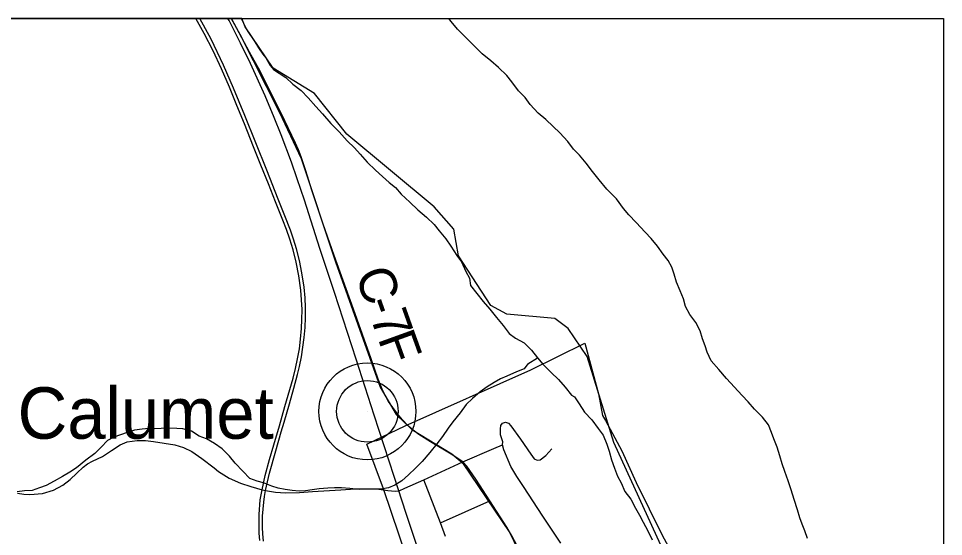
# Model space of a CAD drawing. Extents: x 2.1 to 8.9, y 14.1 to 20.9.
# Drawn here: x 7.48 to 8.9, y 20.105 to 20.9 of the extents above; entities that cross this region are included whole.
import ezdxf

# ---------------------------------------------------------------- set-up
doc = ezdxf.new("R2010")
doc.units = 0
for name, color, linetype in [('Default', 7, 'Continuous'), ('GM_X_Major_River', 7, 'Continuous'), ('GM_X_Minor_River', 7, 'Continuous'), ('GM_X_Rail_Line_Text', 7, 'Continuous'), ('GM_X_State_Location', 7, 'Continuous'), ('GM_X_State_Route', 7, 'Continuous'), ('GM_X_State_Shield', 7, 'Continuous'), ('GM_X_Township_Road', 7, 'Continuous'), ('GM_X_Township_Text', 7, 'Continuous'), ('GM_X_Unincorporated_Text', 7, 'Continuous'), ('SC_Shading1', 7, 'Continuous'), ('SH_Cut_Line', 7, 'Continuous'), ('SH_Data', 7, 'Continuous'), ('TX_P_Misc', 7, 'Continuous')]:
    doc.layers.add(name, color=color, linetype=linetype)

msp = doc.modelspace()

# ---------------------------------------------------------------- linework, layer by layer
at = {"layer": 'Default'}
for p, q in [((7.8225, 20.9), (2.1, 20.9)), ((7.8279, 20.8874), (7.8225, 20.9)), ((7.8709, 20.824), (7.8279, 20.8874)), ((7.9341, 20.7849), (7.8709, 20.824)), ((7.984, 20.7223), (7.9341, 20.7849)), ((8.1182, 20.6111), (7.984, 20.7223)), ((8.1484, 20.5766), (8.1182, 20.6111)), ((8.1552, 20.5359), (8.1484, 20.5766)), ((8.205, 20.4597), (8.1552, 20.5359)), ((8.2298, 20.4464), (8.205, 20.4597)), ((8.3034, 20.4395), (8.2298, 20.4464)), ((8.3237, 20.4245), (8.3034, 20.4395)), ((8.3529, 20.3814), (8.3237, 20.4245)), ((8.3941, 20.2491), (8.3529, 20.3814)), ((8.4717, 20.0797), (8.3941, 20.2491))]:
    msp.add_line(p, q, dxfattribs=at)
at = {"layer": 'GM_X_Rail_Line_Text'}
for p, q in [((7.7649, 20.877), (7.7523, 20.9)), ((7.7754, 20.8683), (7.7584, 20.9)), ((7.7785, 20.8502), (7.7649, 20.877)), ((7.7948, 20.8282), (7.7754, 20.8683)), ((7.7915, 20.8227), (7.7785, 20.8502)), ((7.8037, 20.7945), (7.7915, 20.8227)), ((7.81, 20.7933), (7.7948, 20.8282)), ((7.8152, 20.7667), (7.8037, 20.7945)), ((7.8272, 20.751), (7.81, 20.7933)), ((7.8266, 20.7383), (7.8152, 20.7667)), ((7.844, 20.7094), (7.8272, 20.751)), ((7.8406, 20.7032), (7.8266, 20.7383)), ((7.8609, 20.6671), (7.844, 20.7094)), ((7.8519, 20.6748), (7.8406, 20.7032)), ((7.8634, 20.6465), (7.8519, 20.6748)), ((7.8785, 20.6229), (7.8609, 20.6671)), ((7.8745, 20.6187), (7.8634, 20.6465)), ((7.8889, 20.5972), (7.8785, 20.6229)), ((7.8856, 20.5906), (7.8745, 20.6187)), ((7.8972, 20.5753), (7.8889, 20.5972)), ((7.8911, 20.5764), (7.8856, 20.5906)), ((7.8962, 20.5616), (7.8911, 20.5764)), ((7.902, 20.5613), (7.8972, 20.5753)), ((7.9014, 20.5452), (7.8962, 20.5616)), ((7.9064, 20.5466), (7.902, 20.5613)), ((7.9061, 20.5263), (7.9014, 20.5452)), ((7.9112, 20.5284), (7.9064, 20.5466)), ((7.9101, 20.5052), (7.9061, 20.5263)), ((7.915, 20.5095), (7.9112, 20.5284)), ((7.9184, 20.4879), (7.915, 20.5095)), ((7.9133, 20.4829), (7.9101, 20.5052)), ((7.9145, 20.4682), (7.9133, 20.4829)), ((7.9198, 20.4715), (7.9184, 20.4879)), ((7.9151, 20.4534), (7.9145, 20.4682)), ((7.9204, 20.4565), (7.9198, 20.4715)), ((7.9149, 20.4383), (7.9151, 20.4534)), ((7.9204, 20.441), (7.9204, 20.4565)), ((7.9143, 20.4242), (7.9149, 20.4383)), ((7.9197, 20.4258), (7.9204, 20.441)), ((7.9129, 20.4077), (7.9143, 20.4242)), ((7.9185, 20.4107), (7.9197, 20.4258)), ((7.9166, 20.3955), (7.9185, 20.4107)), ((7.911, 20.393), (7.9129, 20.4077)), ((7.9143, 20.381), (7.9166, 20.3955)), ((7.9082, 20.3779), (7.911, 20.393)), ((7.9113, 20.3659), (7.9143, 20.381)), ((7.905, 20.3629), (7.9082, 20.3779)), ((7.9083, 20.3538), (7.9113, 20.3659)), ((7.9013, 20.3482), (7.905, 20.3629)), ((7.9028, 20.3325), (7.9083, 20.3538)), ((7.8966, 20.3308), (7.9013, 20.3482)), ((7.8889, 20.3045), (7.8966, 20.3308)), ((7.896, 20.3088), (7.9028, 20.3325)), ((7.8875, 20.2805), (7.896, 20.3088)), ((7.8803, 20.2751), (7.8889, 20.3045)), ((7.8831, 20.2656), (7.8875, 20.2805)), ((7.8718, 20.246), (7.8803, 20.2751)), ((7.8748, 20.2367), (7.8831, 20.2656)), ((7.8653, 20.2231), (7.8718, 20.246)), ((7.8651, 20.2024), (7.8748, 20.2367)), ((7.8584, 20.1986), (7.8653, 20.2231)), ((7.8537, 20.1766), (7.8584, 20.1986)), ((7.8591, 20.1756), (7.8651, 20.2024)), ((7.8511, 20.1613), (7.8537, 20.1766)), ((7.8563, 20.1577), (7.8577, 20.1667)), ((7.8577, 20.1667), (7.8591, 20.1756)), ((7.8495, 20.1387), (7.8511, 20.1613)), ((7.8546, 20.1364), (7.8563, 20.1577)), ((7.8492, 20.1199), (7.8495, 20.1387)), ((7.8546, 20.1189), (7.8546, 20.1364)), ((7.8494, 20.1101), (7.8492, 20.1199)), ((7.8505, 20.0989), (7.8494, 20.1101)), ((7.8548, 20.1091), (7.8546, 20.1189)), ((7.8559, 20.0979), (7.8548, 20.1091))]:
    msp.add_line(p, q, dxfattribs=at)
at = {"layer": 'GM_X_State_Location'}
for p, q in [((7.8215, 20.9), (7.8307, 20.8817)), ((8.1442, 20.8953), (8.1404, 20.9)), ((8.1539, 20.8834), (8.1442, 20.8953)), ((7.8307, 20.8817), (7.8425, 20.8642)), ((8.1666, 20.8711), (8.1539, 20.8834)), ((7.8425, 20.8642), (7.8481, 20.8551)), ((8.1798, 20.8577), (8.1666, 20.8711)), ((7.8481, 20.8551), (7.8551, 20.8451)), ((8.1918, 20.8458), (8.1798, 20.8577)), ((7.8551, 20.8451), (7.8594, 20.8394)), ((7.8594, 20.8394), (7.8664, 20.8281)), ((8.2052, 20.835), (8.1918, 20.8458)), ((8.2168, 20.825), (8.2052, 20.835)), ((7.8664, 20.8281), (7.8712, 20.822)), ((7.8712, 20.822), (7.8904, 20.8097)), ((8.2295, 20.8124), (8.2168, 20.825)), ((7.8904, 20.8097), (7.9012, 20.7993)), ((8.2373, 20.8026), (8.2295, 20.8124)), ((7.9012, 20.7993), (7.9136, 20.7893)), ((8.2474, 20.7892), (8.2373, 20.8026)), ((7.9136, 20.7893), (7.9244, 20.7785)), ((7.9244, 20.7785), (7.9364, 20.7651)), ((8.2579, 20.7788), (8.2474, 20.7892)), ((8.2656, 20.7679), (8.2579, 20.7788)), ((7.9364, 20.7651), (7.9465, 20.7539)), ((8.2776, 20.7545), (8.2656, 20.7679)), ((7.9465, 20.7539), (7.9593, 20.739)), ((8.2892, 20.7448), (8.2776, 20.7545)), ((7.9593, 20.739), (7.972, 20.7263)), ((8.3008, 20.7341), (8.2892, 20.7448)), ((7.972, 20.7263), (7.9844, 20.7125)), ((8.3108, 20.7248), (8.3008, 20.7341)), ((8.3232, 20.711), (8.3108, 20.7248)), ((7.9844, 20.7125), (7.9956, 20.7013)), ((8.3321, 20.6997), (8.3232, 20.711)), ((7.9956, 20.7013), (8.0045, 20.6916)), ((8.341, 20.6901), (8.3321, 20.6997)), ((8.0045, 20.6916), (8.015, 20.6793)), ((8.015, 20.6793), (8.0281, 20.6671)), ((8.3515, 20.6781), (8.341, 20.6901)), ((8.3612, 20.6654), (8.3515, 20.6781)), ((8.0281, 20.6671), (8.0389, 20.6574)), ((8.3713, 20.6523), (8.3612, 20.6654)), ((8.0389, 20.6574), (8.0489, 20.6485)), ((8.3833, 20.6381), (8.3713, 20.6523)), ((8.0489, 20.6485), (8.0585, 20.6407)), ((8.0585, 20.6407), (8.0674, 20.6306)), ((8.398, 20.6232), (8.3833, 20.6381)), ((8.0674, 20.6306), (8.0809, 20.6184)), ((8.4085, 20.6086), (8.398, 20.6232)), ((8.0809, 20.6184), (8.0929, 20.6065)), ((8.4171, 20.5989), (8.4085, 20.6086)), ((8.0929, 20.6065), (8.1064, 20.5953)), ((8.1064, 20.5953), (8.118, 20.5838)), ((8.4279, 20.587), (8.4171, 20.5989)), ((8.118, 20.5838), (8.1258, 20.5741)), ((8.4418, 20.5721), (8.4279, 20.587)), ((8.1258, 20.5741), (8.1358, 20.5621)), ((8.4511, 20.5624), (8.4418, 20.5721)), ((8.1358, 20.5621), (8.1436, 20.5505)), ((8.1436, 20.5505), (8.1528, 20.5364)), ((8.4608, 20.5508), (8.4511, 20.5624)), ((8.4698, 20.5385), (8.4608, 20.5508)), ((8.1528, 20.5364), (8.1598, 20.5264)), ((8.4772, 20.5284), (8.4698, 20.5385)), ((8.1598, 20.5264), (8.1667, 20.512)), ((8.483, 20.5182), (8.4772, 20.5284)), ((8.1667, 20.512), (8.1722, 20.5017)), ((8.4863, 20.5077), (8.483, 20.5182)), ((8.4903, 20.4952), (8.4863, 20.5077)), ((8.1722, 20.5017), (8.1736, 20.4904)), ((8.4955, 20.4821), (8.4903, 20.4952)), ((8.1736, 20.4904), (8.1833, 20.4781)), ((8.501, 20.47), (8.4955, 20.4821)), ((8.1833, 20.4781), (8.193, 20.4657)), ((8.193, 20.4657), (8.2035, 20.4538)), ((8.5039, 20.4579), (8.501, 20.47)), ((8.2035, 20.4538), (8.2136, 20.4411)), ((8.5106, 20.4456), (8.5039, 20.4579)), ((8.2136, 20.4411), (8.2237, 20.4287)), ((8.5195, 20.4336), (8.5106, 20.4456)), ((8.2237, 20.4287), (8.233, 20.4168)), ((8.5262, 20.4208), (8.5195, 20.4336)), ((8.233, 20.4168), (8.243, 20.4094)), ((8.243, 20.4094), (8.2564, 20.4021)), ((8.5299, 20.4084), (8.5262, 20.4208)), ((8.5342, 20.3978), (8.5299, 20.4084)), ((8.2564, 20.4021), (8.2672, 20.3909)), ((8.5371, 20.388), (8.5342, 20.3978)), ((8.2672, 20.3909), (8.2769, 20.3793)), ((8.5434, 20.3749), (8.5371, 20.388)), ((8.2769, 20.3793), (8.2847, 20.3696)), ((8.2847, 20.3696), (8.2974, 20.3569)), ((8.555, 20.3614), (8.5434, 20.3749)), ((8.2974, 20.3569), (8.309, 20.3462)), ((8.5667, 20.3476), (8.555, 20.3614)), ((8.309, 20.3462), (8.3191, 20.3342)), ((8.5907, 20.3215), (8.5667, 20.3476)), ((8.3191, 20.3342), (8.3288, 20.3222)), ((8.3288, 20.3222), (8.3334, 20.3193)), ((8.3334, 20.3193), (8.3404, 20.3088)), ((8.3404, 20.3088), (8.3486, 20.2957)), ((8.5999, 20.3118), (8.5907, 20.3215)), ((8.61, 20.3003), (8.5999, 20.3118)), ((8.3486, 20.2957), (8.3599, 20.2841)), ((8.622, 20.288), (8.61, 20.3003)), ((8.3599, 20.2841), (8.37, 20.2707)), ((8.6313, 20.2764), (8.622, 20.288)), ((8.37, 20.2707), (8.3774, 20.2606)), ((8.6361, 20.2647), (8.6313, 20.2764)), ((8.3774, 20.2606), (8.3829, 20.2466)), ((8.6397, 20.2549), (8.6361, 20.2647)), ((8.6445, 20.2421), (8.6397, 20.2549)), ((8.3829, 20.2466), (8.3865, 20.2361)), ((8.6489, 20.2289), (8.6445, 20.2421)), ((8.3865, 20.2361), (8.3902, 20.2225)), ((8.6522, 20.2165), (8.6489, 20.2289)), ((8.3902, 20.2225), (8.395, 20.2097)), ((8.395, 20.2097), (8.3994, 20.1976)), ((8.6562, 20.2048), (8.6522, 20.2165)), ((8.3994, 20.1976), (8.4049, 20.1875)), ((8.6614, 20.1905), (8.6562, 20.2048)), ((8.4049, 20.1875), (8.4109, 20.1743)), ((8.6662, 20.1769), (8.6614, 20.1905)), ((8.4109, 20.1743), (8.4202, 20.1624)), ((8.6707, 20.1618), (8.6662, 20.1769)), ((8.4202, 20.1624), (8.4273, 20.1485)), ((8.6759, 20.146), (8.6707, 20.1618)), ((8.4273, 20.1485), (8.4332, 20.138)), ((8.6792, 20.1339), (8.6759, 20.146)), ((8.4332, 20.138), (8.439, 20.1271)), ((8.439, 20.1271), (8.4461, 20.1136)), ((8.6831, 20.1241), (8.6792, 20.1339)), ((8.6871, 20.1139), (8.6831, 20.1241)), ((8.4461, 20.1136), (8.4525, 20.1)), ((8.6912, 20.1019), (8.6871, 20.1139))]:
    msp.add_line(p, q, dxfattribs=at)
at = {"layer": 'GM_X_State_Route'}
for radius in [0.0744, 0.0472]:
    msp.add_circle((8.0155, 20.2971), radius, dxfattribs=at)
at = {"layer": 'GM_X_State_Shield'}
for p, q in [((7.8346, 20.8483), (7.8068, 20.9)), ((7.8508, 20.8192), (7.8346, 20.8483)), ((7.8615, 20.7979), (7.8508, 20.8192)), ((7.883, 20.7545), (7.8615, 20.7979)), ((7.9052, 20.7089), (7.883, 20.7545)), ((7.9099, 20.6984), (7.9052, 20.7089)), ((7.9138, 20.6879), (7.9099, 20.6984)), ((7.921, 20.6664), (7.9138, 20.6879)), ((7.9303, 20.6365), (7.921, 20.6664)), ((7.9474, 20.5844), (7.9303, 20.6365)), ((7.9646, 20.5364), (7.9474, 20.5844)), ((7.9784, 20.4978), (7.9646, 20.5364)), ((7.9943, 20.4538), (7.9784, 20.4978)), ((8.008, 20.4149), (7.9943, 20.4538)), ((8.0211, 20.3779), (8.008, 20.4149)), ((8.032, 20.3465), (8.0211, 20.3779)), ((8.0392, 20.3286), (8.032, 20.3465)), ((8.0481, 20.3125), (8.0392, 20.3286)), ((8.0543, 20.3028), (8.0481, 20.3125)), ((8.0615, 20.2934), (8.0543, 20.3028)), ((8.0689, 20.2844), (8.0615, 20.2934)), ((8.0788, 20.2746), (8.0689, 20.2844)), ((8.0856, 20.2683), (8.0788, 20.2746)), ((8.0947, 20.2617), (8.0856, 20.2683)), ((7.6469, 20.2501), (7.6622, 20.2524)), ((7.6622, 20.2524), (7.675, 20.2523)), ((7.675, 20.2523), (7.6872, 20.2507)), ((8.1122, 20.2506), (8.0947, 20.2617)), ((7.6228, 20.2371), (7.6361, 20.2457)), ((7.6361, 20.2457), (7.6469, 20.2501)), ((7.6872, 20.2507), (7.72, 20.2455)), ((7.72, 20.2455), (7.7331, 20.2419)), ((7.7331, 20.2419), (7.7457, 20.2354)), ((8.1443, 20.2316), (8.1122, 20.2506)), ((7.5934, 20.2208), (7.609, 20.2277)), ((7.609, 20.2277), (7.6228, 20.2371)), ((7.7457, 20.2354), (7.7611, 20.2249)), ((7.7611, 20.2249), (7.78, 20.2104)), ((8.1622, 20.2196), (8.1443, 20.2316)), ((7.5696, 20.2021), (7.579, 20.2113)), ((7.579, 20.2113), (7.586, 20.2167)), ((7.586, 20.2167), (7.5934, 20.2208)), ((7.78, 20.2104), (7.7871, 20.2049)), ((8.1021, 20.1918), (8.1622, 20.2196)), ((8.1682, 20.213), (8.1622, 20.2196)), ((8.1819, 20.1931), (8.1682, 20.213)), ((7.5591, 20.1924), (7.5696, 20.2021)), ((7.7871, 20.2049), (7.8031, 20.1946)), ((7.5334, 20.1762), (7.5481, 20.184)), ((7.5481, 20.184), (7.5591, 20.1924)), ((7.8031, 20.1946), (7.8207, 20.1869)), ((7.8207, 20.1869), (7.8364, 20.1816)), ((7.8364, 20.1816), (7.8537, 20.1766)), ((8.0731, 20.1792), (8.1021, 20.1918)), ((8.2033, 20.1598), (8.1819, 20.1931)), ((7.4784, 20.1716), (7.4881, 20.1701)), ((7.4881, 20.1701), (7.4974, 20.1693)), ((7.4974, 20.1693), (7.5168, 20.171)), ((7.5168, 20.171), (7.5334, 20.1762)), ((7.8537, 20.1766), (7.8591, 20.1756)), ((7.8591, 20.1756), (7.8745, 20.1732)), ((7.8745, 20.1732), (7.8895, 20.1723)), ((7.8895, 20.1723), (7.9111, 20.1727)), ((7.9111, 20.1727), (7.9313, 20.1741)), ((7.9313, 20.1741), (7.9746, 20.1769)), ((7.9746, 20.1769), (7.9967, 20.1783)), ((7.9967, 20.1783), (8.0114, 20.1784)), ((8.0114, 20.1784), (8.0155, 20.1783)), ((8.0155, 20.1783), (8.0297, 20.178)), ((8.0297, 20.178), (8.0471, 20.1759)), ((8.0471, 20.1759), (8.058, 20.1745)), ((8.058, 20.1745), (8.0641, 20.1753)), ((8.0641, 20.1753), (8.0731, 20.1792)), ((8.2296, 20.1193), (8.2033, 20.1598)), ((8.2374, 20.1063), (8.2296, 20.1193)), ((8.2452, 20.091), (8.2374, 20.1063))]:
    msp.add_line(p, q, dxfattribs=at)
at = {"layer": 'GM_X_Township_Road'}
for p, q in [((8.2662, 20.3608), (8.3492, 20.4017)), ((8.3492, 20.4017), (8.3704, 20.3238)), ((8.0734, 20.2747), (8.2662, 20.3608)), ((8.3704, 20.3238), (8.3764, 20.2906)), ((8.3764, 20.2906), (8.3812, 20.2831)), ((8.3812, 20.2831), (8.4062, 20.2365)), ((8.0144, 20.2466), (8.0734, 20.2747)), ((8.0402, 20.1783), (8.0144, 20.2466)), ((8.4062, 20.2365), (8.4283, 20.1879)), ((8.4283, 20.1879), (8.4681, 20.1072)), ((8.1055, 19.9861), (8.0402, 20.1783)), ((8.4681, 20.1072), (8.4996, 20.049))]:
    msp.add_line(p, q, dxfattribs=at)
at = {"layer": 'GM_X_Township_Text'}
msp.add_line((8.0155, 20.2971), (8.0155, 20.2971), dxfattribs=at)
at = {"layer": 'GM_X_Unincorporated_Text'}
for p, q in [((8.223, 20.2789), (8.2274, 20.2807)), ((8.2274, 20.2807), (8.2321, 20.2791)), ((8.2196, 20.2705), (8.2203, 20.2752)), ((8.2196, 20.2671), (8.2196, 20.2705)), ((8.2201, 20.2609), (8.2196, 20.2671)), ((8.2203, 20.2752), (8.223, 20.2789)), ((8.2321, 20.2791), (8.2357, 20.2749)), ((8.2357, 20.2749), (8.2506, 20.2546)), ((8.2232, 20.2504), (8.2201, 20.2609)), ((8.2506, 20.2546), (8.2662, 20.2314)), ((8.1622, 20.2196), (8.2094, 20.2402)), ((8.2094, 20.2402), (8.223, 20.2456)), ((8.223, 20.2456), (8.2232, 20.2504)), ((8.225, 20.2379), (8.223, 20.2456)), ((8.2358, 20.2126), (8.225, 20.2379)), ((8.2892, 20.2296), (8.2986, 20.2398)), ((8.2662, 20.2314), (8.2717, 20.2244)), ((8.2717, 20.2244), (8.2764, 20.2223)), ((8.2808, 20.2228), (8.2892, 20.2296)), ((8.2449, 20.1973), (8.2358, 20.2126)), ((8.2764, 20.2223), (8.2808, 20.2228)), ((8.2552, 20.1816), (8.2449, 20.1973)), ((8.1276, 20.1259), (8.1021, 20.1918)), ((8.2851, 20.1362), (8.2552, 20.1816)), ((8.1276, 20.1259), (8.2033, 20.1598)), ((8.1356, 20.1051), (8.1276, 20.1259)), ((8.3123, 20.0947), (8.2851, 20.1362))]:
    msp.add_line(p, q, dxfattribs=at)
at = {"layer": 'SC_Shading1'}
for p, q in [((7.8031, 20.8968), (7.8014, 20.9)), ((7.8205, 20.8622), (7.8031, 20.8968)), ((7.8062, 20.9), (7.8197, 20.8759)), ((7.8197, 20.8759), (7.8804, 20.7559)), ((7.8358, 20.8308), (7.8205, 20.8622)), ((7.8585, 20.7813), (7.8358, 20.8308)), ((7.8724, 20.7482), (7.8585, 20.7813)), ((7.8804, 20.7559), (7.9138, 20.6851)), ((7.8829, 20.7214), (7.8724, 20.7482)), ((7.8988, 20.6793), (7.8829, 20.7214)), ((7.9079, 20.6542), (7.8988, 20.6793)), ((7.9138, 20.6851), (7.9664, 20.5265)), ((7.9187, 20.6212), (7.9079, 20.6542)), ((7.9426, 20.5472), (7.9187, 20.6212)), ((7.965, 20.4793), (7.9426, 20.5472)), ((7.9664, 20.5265), (8.035, 20.3342)), ((7.9983, 20.3771), (7.965, 20.4793)), ((8.0259, 20.2913), (7.9983, 20.3771)), ((8.035, 20.3342), (8.0598, 20.2924)), ((8.0566, 20.1971), (8.0259, 20.2913)), ((8.0598, 20.2924), (8.0838, 20.2692)), ((8.0838, 20.2692), (8.1451, 20.2321)), ((8.1451, 20.2321), (8.1616, 20.2181)), ((8.1616, 20.2181), (8.2344, 20.1106)), ((8.0752, 20.1403), (8.0566, 20.1971)), ((8.0921, 20.0895), (8.0752, 20.1403)), ((8.2344, 20.1106), (8.3564, 19.8562))]:
    msp.add_line(p, q, dxfattribs=at)
at = {"layer": 'SH_Cut_Line'}
for p, q in [((7.8225, 20.9), (2.1, 20.9)), ((7.8279, 20.8874), (7.8225, 20.9)), ((7.8709, 20.824), (7.8279, 20.8874)), ((7.9341, 20.7849), (7.8709, 20.824)), ((7.984, 20.7223), (7.9341, 20.7849)), ((8.1182, 20.6111), (7.984, 20.7223)), ((8.1484, 20.5766), (8.1182, 20.6111)), ((8.1552, 20.5359), (8.1484, 20.5766)), ((8.205, 20.4597), (8.1552, 20.5359)), ((8.2298, 20.4464), (8.205, 20.4597)), ((8.3034, 20.4395), (8.2298, 20.4464)), ((8.3237, 20.4245), (8.3034, 20.4395)), ((8.3529, 20.3814), (8.3237, 20.4245)), ((8.3941, 20.2491), (8.3529, 20.3814)), ((8.4717, 20.0797), (8.3941, 20.2491))]:
    msp.add_line(p, q, dxfattribs=at)
at = {"layer": 'SH_Data'}
for p, q in [((2.1, 20.9), (8.9, 20.9)), ((2.1, 20.9), (8.9, 20.9)), ((8.9, 20.9), (8.9, 14.1)), ((8.9, 20.9), (8.9, 14.1))]:
    msp.add_line(p, q, dxfattribs=at)
at = {"layer": 'TX_P_Misc'}
for p, q in [((8.2618, 20.3703), (8.256, 20.3626)), ((8.2618, 20.3703), (8.2769, 20.3793)), ((8.2298, 20.3512), (8.2196, 20.3468)), ((8.2444, 20.3577), (8.2298, 20.3512)), ((8.256, 20.3626), (8.2444, 20.3577)), ((8.2099, 20.3416), (8.1994, 20.3348)), ((8.2196, 20.3468), (8.2099, 20.3416)), ((8.1886, 20.3273), (8.1767, 20.3167)), ((8.1994, 20.3348), (8.1886, 20.3273)), ((8.1767, 20.3167), (8.1671, 20.3077)), ((8.1579, 20.2949), (8.1465, 20.2809)), ((8.1671, 20.3077), (8.1579, 20.2949)), ((8.1465, 20.2809), (8.1396, 20.2712)), ((7.6578, 20.2681), (7.6469, 20.2647)), ((7.6699, 20.2699), (7.6578, 20.2681)), ((7.6798, 20.2706), (7.6699, 20.2699)), ((7.6893, 20.2704), (7.6798, 20.2706)), ((7.6988, 20.2707), (7.6893, 20.2704)), ((7.7109, 20.2714), (7.6988, 20.2707)), ((7.7227, 20.271), (7.7109, 20.2714)), ((7.7322, 20.2701), (7.7227, 20.271)), ((7.7456, 20.2666), (7.7322, 20.2701)), ((7.7572, 20.2593), (7.7456, 20.2666)), ((8.1396, 20.2712), (8.1308, 20.2584)), ((7.6164, 20.2525), (7.6068, 20.2423)), ((7.6261, 20.2577), (7.6164, 20.2525)), ((7.6363, 20.261), (7.6261, 20.2577)), ((7.6469, 20.2647), (7.6363, 20.261)), ((7.7684, 20.2547), (7.7572, 20.2593)), ((7.7807, 20.2478), (7.7684, 20.2547)), ((8.1308, 20.2584), (8.122, 20.2472)), ((7.6068, 20.2423), (7.5968, 20.2326)), ((7.7927, 20.2398), (7.7807, 20.2478)), ((7.8037, 20.2286), (7.7927, 20.2398)), ((8.122, 20.2472), (8.1113, 20.2339)), ((7.5968, 20.2326), (7.583, 20.2223)), ((7.8127, 20.2175), (7.8037, 20.2286)), ((8.1113, 20.2339), (8.0996, 20.2203)), ((7.5689, 20.2105), (7.5585, 20.2038)), ((7.583, 20.2223), (7.5689, 20.2105)), ((7.8244, 20.2052), (7.8127, 20.2175)), ((8.0896, 20.2098), (8.0785, 20.1996)), ((8.0996, 20.2203), (8.0896, 20.2098)), ((7.5472, 20.1974), (7.5345, 20.1902)), ((7.5585, 20.2038), (7.5472, 20.1974)), ((7.835, 20.1941), (7.8244, 20.2052)), ((8.0785, 20.1996), (8.0684, 20.1906)), ((7.5225, 20.1834), (7.512, 20.1797)), ((7.5345, 20.1902), (7.5225, 20.1834)), ((7.8461, 20.1899), (7.835, 20.1941)), ((7.8561, 20.1875), (7.8461, 20.1899)), ((7.8688, 20.1821), (7.8561, 20.1875)), ((7.8787, 20.179), (7.8688, 20.1821)), ((8.0576, 20.1838), (8.0478, 20.1797)), ((8.0684, 20.1906), (8.0576, 20.1838)), ((7.4889, 20.1749), (7.4779, 20.1738)), ((7.5007, 20.1759), (7.4889, 20.1749)), ((7.512, 20.1797), (7.5007, 20.1759)), ((7.8891, 20.177), (7.8787, 20.179)), ((7.9001, 20.1757), (7.8891, 20.177)), ((7.9108, 20.1745), (7.9001, 20.1757)), ((7.9206, 20.1751), (7.9108, 20.1745)), ((7.9305, 20.1766), (7.9206, 20.1751)), ((7.9415, 20.178), (7.9305, 20.1766)), ((7.9547, 20.1791), (7.9415, 20.178)), ((7.965, 20.1798), (7.9547, 20.1791)), ((7.9756, 20.1797), (7.965, 20.1798)), ((7.9886, 20.1789), (7.9756, 20.1797)), ((8.0027, 20.1774), (7.9886, 20.1789)), ((8.0243, 20.1776), (8.0027, 20.1774)), ((8.0361, 20.1779), (8.0243, 20.1776)), ((8.0478, 20.1797), (8.0361, 20.1779))]:
    msp.add_line(p, q, dxfattribs=at)

# ---------------------------------------------------------------- texts
at = {"layer": 'GM_X_Major_River'}
msp.add_text('Calumet', height=0.07898, rotation=0, dxfattribs=at).set_placement((7.4784, 20.2551))
at = {"layer": 'GM_X_Minor_River'}
for s, rotation, p in [('C', 289.5778, (7.996, 20.5077)), ('-', 289.5779, (8.0116, 20.4641)), ('7', 289.5858, (8.0193, 20.4423)), ('F', 289.876, (8.0311, 20.4092))]:
    msp.add_text(s, height=0.0568, rotation=rotation, dxfattribs=at).set_placement(p)

doc.saveas('drawing.dxf')
